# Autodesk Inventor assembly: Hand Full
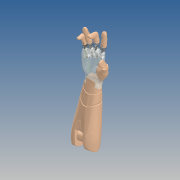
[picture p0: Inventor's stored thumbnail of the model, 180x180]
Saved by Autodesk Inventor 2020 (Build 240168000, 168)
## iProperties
Created: 2019-10
Part Number: Hand Full
Document SubType Name: Assembly
Designer: yello
Author: yello
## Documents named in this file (20)
- C:\Users\yello\Documents\Mechanical Hand\Prototype 2 (Realistic Hand)\Hand Full.iam
- C:\Users\yello\Documents\Mechanical Hand\Prototype 2 (Realistic Hand)\Palm.ipt
- C:\Users\yello\Documents\Mechanical Hand\Prototype 2 (Realistic Hand)\Wrist Rotation.ipt
- C:\Users\yello\Documents\Mechanical Hand\Prototype 2 (Realistic Hand)\Arm to Wrist Connection.ipt
- C:\Users\yello\Documents\Mechanical Hand\Prototype 2 (Realistic Hand)\Arm.ipt
- C:\Users\yello\Documents\Mechanical Hand\Prototype 2 (Realistic Hand)\Segment Thumb Finger Bottom.ipt
- C:\Users\yello\Documents\Mechanical Hand\Prototype 2 (Realistic Hand)\Segment Thumb Finger Middle.ipt
- C:\Users\yello\Documents\Mechanical Hand\Prototype 2 (Realistic Hand)\Segment Thumb Finger Top.ipt
- C:\Users\yello\Documents\Mechanical Hand\Prototype 2 (Realistic Hand)\Segment Index Finger Middle.ipt
- C:\Users\yello\Documents\Mechanical Hand\Prototype 2 (Realistic Hand)\Segment Index Finger Top.ipt
- C:\Users\yello\Documents\Mechanical Hand\Prototype 2 (Realistic Hand)\Segment Middle Finger Middle.ipt
- C:\Users\yello\Documents\Mechanical Hand\Prototype 2 (Realistic Hand)\Segment Middle Finger Top.ipt
- C:\Users\yello\Documents\Mechanical Hand\Prototype 2 (Realistic Hand)\Segment Ring Finger Middle.ipt
- C:\Users\yello\Documents\Mechanical Hand\Prototype 2 (Realistic Hand)\Segment Ring Finger Top.ipt
- C:\Users\yello\Documents\Mechanical Hand\Prototype 2 (Realistic Hand)\Segment Pinkie Finger Middle.ipt
- C:\Users\yello\Documents\Mechanical Hand\Prototype 2 (Realistic Hand)\Segment Pinkie Finger Top.ipt
- C:\Users\yello\Documents\Mechanical Hand\Prototype 2 (Realistic Hand)\Segment Index Finger Bottom Ball.iam
- C:\Users\yello\Documents\Mechanical Hand\Prototype 2 (Realistic Hand)\Segment Middle Finger Bottom Ball.iam
- C:\Users\yello\Documents\Mechanical Hand\Prototype 2 (Realistic Hand)\Segment Ring Finger Bottom Ball.iam
- C:\Users\yello\Documents\Mechanical Hand\Prototype 2 (Realistic Hand)\Segment Pinkie Finger Bottom Ball.iam
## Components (19 placed, 19 different names)
1. Palm:1 — Rotational:1, Rotational:2, Rotational:17, Rotational:18, Rotational:19, Rotational:20
2. Wrist Rotation:1 — Rotational:1, Mate:1, Mate:2, Mate:4
3. Arm to Wrist Connection:1 — Mate:1, Mate:2, Mate:3
4. Arm:1 — Mate:3, Mate:4
5. Segment Thumb Finger Bottom:1 — Rotational:2, Rotational:3
6. Segment Thumb Finger Middle:1 — Rotational:3, Rotational:4
7. Segment Thumb Finger Top:1 — Rotational:4
8. Segment Index Finger Middle:1 — Rotational:24, Rotational:25
9. Segment Index Finger Top:1 — Rotational:25
10. Segment Middle Finger Middle:1 — Rotational:10, Rotational:23
11. Segment Middle Finger Top:1 — Rotational:10
12. Segment Ring Finger Middle:1 — Rotational:13, Rotational:22
13. Segment Ring Finger Top:1 — Rotational:13
14. Segment Pinkie Finger Middle:1 — Rotational:16, Rotational:21
15. Segment Pinkie Finger Top:1 — Rotational:16
16. Segment Index Finger Bottom Ball:1 [sub-assembly] — Rotational:17, Rotational:24
17. Segment Middle Finger Bottom Ball:1 [sub-assembly] — Rotational:18, Rotational:23
18. Segment Ring Finger Bottom Ball:1 [sub-assembly] — Rotational:19, Rotational:22
19. Segment Pinkie Finger Bottom Ball:1 [sub-assembly] — Rotational:20, Rotational:21
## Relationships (20: RevoluteJoint 16, Mate 4)
- Rotational:1 [RevoluteJoint]: Palm:1 ↔ Wrist Rotation:1
- Mate:1: Wrist Rotation:1 ↔ Arm to Wrist Connection:1
- Mate:2: Wrist Rotation:1 ↔ Arm to Wrist Connection:1
- Mate:3: Arm to Wrist Connection:1 ↔ Arm:1
- Mate:4: Wrist Rotation:1 ↔ Arm:1
- Rotational:2 [RevoluteJoint]: Palm:1 ↔ Segment Thumb Finger Bottom:1
- Rotational:3 [RevoluteJoint]: Segment Thumb Finger Bottom:1 ↔ Segment Thumb Finger Middle:1
- Rotational:4 [RevoluteJoint]: Segment Thumb Finger Middle:1 ↔ Segment Thumb Finger Top:1
- Rotational:10 [RevoluteJoint]: Segment Middle Finger Middle:1 ↔ Segment Middle Finger Top:1
- Rotational:13 [RevoluteJoint]: Segment Ring Finger Middle:1 ↔ Segment Ring Finger Top:1
- Rotational:16 [RevoluteJoint]: Segment Pinkie Finger Middle:1 ↔ Segment Pinkie Finger Top:1
- Rotational:17 [RevoluteJoint]: Palm:1 ↔ Segment Index Finger Bottom Ball:1
- Rotational:18 [RevoluteJoint]: Palm:1 ↔ Segment Middle Finger Bottom Ball:1
- Rotational:19 [RevoluteJoint]: Palm:1 ↔ Segment Ring Finger Bottom Ball:1
- Rotational:20 [RevoluteJoint]: Palm:1 ↔ Segment Pinkie Finger Bottom Ball:1
- Rotational:21 [RevoluteJoint]: Segment Pinkie Finger Middle:1 ↔ Segment Pinkie Finger Bottom Ball:1
- Rotational:22 [RevoluteJoint]: Segment Ring Finger Middle:1 ↔ Segment Ring Finger Bottom Ball:1
- Rotational:23 [RevoluteJoint]: Segment Middle Finger Middle:1 ↔ Segment Middle Finger Bottom Ball:1
- Rotational:24 [RevoluteJoint]: Segment Index Finger Middle:1 ↔ Segment Index Finger Bottom Ball:1
- Rotational:25 [RevoluteJoint]: Segment Index Finger Middle:1 ↔ Segment Index Finger Top:1
